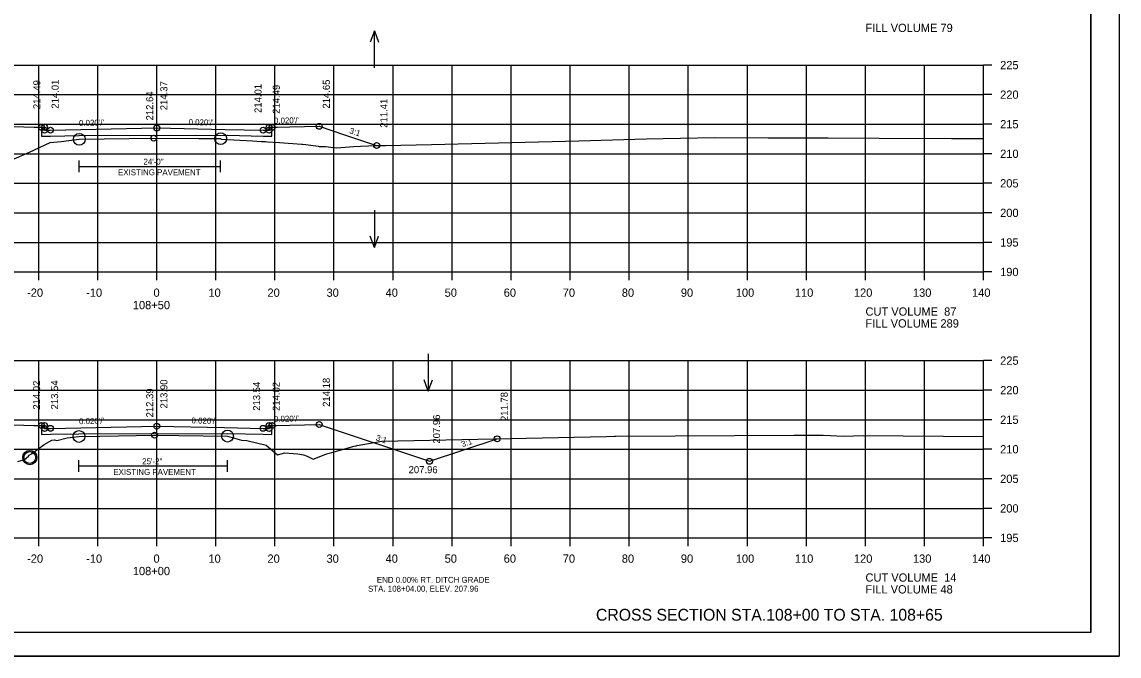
# Model space of a CAD drawing. Extents: x 1368968 to 1369915, y 377395 to 380381.
# Drawn here: x 1369115.3 to 1369301.1, y 379327.7 to 379435 of the extents above; entities that cross this region are included whole.
import ezdxf

# ---------------------------------------------------------------- set-up
doc = ezdxf.new("R2010")
doc.units = 0
for name, color, linetype in [('S_BORDER_NO_PLOT', 7, 'Continuous'), ('S_BREAKLINE_ANNOT', 7, 'Continuous'), ('S_BRIDGE', 7, 'Continuous'), ('S_BRIDGE_ANNOT', 7, 'Continuous'), ('S_CONTOUR_MAJOR', 7, 'Continuous'), ('S_CONTOUR_MINOR', 7, 'Continuous'), ('S_CROSS_DRAIN', 7, 'Continuous'), ('S_CTL_TABLE', 7, 'Continuous'), ('S_CURB_ANNOT', 7, 'Continuous'), ('S_DITCHLINE_ANNOT', 7, 'Continuous'), ('S_DROP_INLET', 7, 'Continuous'), ('S_EXIST_ROW_ANNOT', 7, 'Continuous'), ('S_EXISTING_ALIGNMENT', 7, 'Continuous'), ('S_EXISTING_ALIGNMENT_ANNOT', 7, 'Continuous'), ('S_FENCE', 7, 'Continuous')]:
    doc.layers.add(name, color=color, linetype=linetype)

msp = doc.modelspace()

# ---------------------------------------------------------------- linework, layer by layer
at = {"layer": 'S_BORDER_NO_PLOT'}
for points in [[(1369118.62, 379417.2), (1369118.63, 379415.69), (1369120.13, 379415.72), (1369125, 379415.82), (1369150.13, 379415.84), (1369156.13, 379415.72), (1369157.63, 379415.69), (1369157.64, 379417.2)], [(1369118.62, 379366.74), (1369118.63, 379365.23), (1369120.13, 379365.26), (1369124.95, 379365.35), (1369150.13, 379365.38), (1369156.13, 379365.26), (1369157.63, 379365.23), (1369157.64, 379366.74)]]:
    msp.add_lwpolyline(points, dxfattribs=at)
at = {"layer": 'S_BREAKLINE_ANNOT'}
for p, q in [((1369278.13, 379392.72), (1369278.13, 379427.72)), ((1369279.53, 379427.72), (1369278.13, 379427.72)), ((1369279.53, 379422.72), (1369278.13, 379422.72)), ((1369279.53, 379417.72), (1369278.13, 379417.72)), ((1369279.53, 379412.72), (1369278.13, 379412.72)), ((1369279.53, 379407.72), (1369278.13, 379407.72)), ((1369279.53, 379402.72), (1369278.13, 379402.72)), ((1369279.53, 379397.72), (1369278.13, 379397.72)), ((1368998.13, 379392.72), (1369278.13, 379392.72)), ((1369118.13, 379391.32), (1369118.13, 379392.72)), ((1369128.13, 379391.32), (1369128.13, 379392.72)), ((1369138.13, 379391.32), (1369138.13, 379392.72)), ((1369148.13, 379391.32), (1369148.13, 379392.72)), ((1369158.13, 379391.32), (1369158.13, 379392.72)), ((1369168.13, 379391.32), (1369168.13, 379392.72)), ((1369178.13, 379391.32), (1369178.13, 379392.72)), ((1369188.13, 379391.32), (1369188.13, 379392.72)), ((1369198.13, 379391.32), (1369198.13, 379392.72)), ((1369208.13, 379391.32), (1369208.13, 379392.72)), ((1369218.13, 379391.32), (1369218.13, 379392.72)), ((1369228.13, 379391.32), (1369228.13, 379392.72)), ((1369238.13, 379391.32), (1369238.13, 379392.72)), ((1369248.13, 379391.32), (1369248.13, 379392.72)), ((1369258.13, 379391.32), (1369258.13, 379392.72)), ((1369268.13, 379391.32), (1369268.13, 379392.72)), ((1369278.13, 379391.32), (1369278.13, 379392.72)), ((1369279.53, 379392.72), (1369278.13, 379392.72)), ((1369278.13, 379347.72), (1369278.13, 379377.72)), ((1369279.53, 379377.72), (1369278.13, 379377.72)), ((1369279.53, 379372.72), (1369278.13, 379372.72)), ((1369279.53, 379367.72), (1369278.13, 379367.72)), ((1369279.53, 379362.72), (1369278.13, 379362.72)), ((1369279.53, 379357.72), (1369278.13, 379357.72)), ((1369279.53, 379352.72), (1369278.13, 379352.72)), ((1368998.13, 379347.72), (1369278.13, 379347.72)), ((1369118.13, 379346.32), (1369118.13, 379347.72)), ((1369128.13, 379346.32), (1369128.13, 379347.72)), ((1369138.13, 379346.32), (1369138.13, 379347.72)), ((1369148.13, 379346.32), (1369148.13, 379347.72)), ((1369158.13, 379346.32), (1369158.13, 379347.72)), ((1369168.13, 379346.32), (1369168.13, 379347.72)), ((1369178.13, 379346.32), (1369178.13, 379347.72)), ((1369188.13, 379346.32), (1369188.13, 379347.72)), ((1369198.13, 379346.32), (1369198.13, 379347.72)), ((1369208.13, 379346.32), (1369208.13, 379347.72)), ((1369218.13, 379346.32), (1369218.13, 379347.72)), ((1369228.13, 379346.32), (1369228.13, 379347.72)), ((1369238.13, 379346.32), (1369238.13, 379347.72)), ((1369248.13, 379346.32), (1369248.13, 379347.72)), ((1369258.13, 379346.32), (1369258.13, 379347.72)), ((1369268.13, 379346.32), (1369268.13, 379347.72)), ((1369278.13, 379346.32), (1369278.13, 379347.72)), ((1369279.53, 379347.72), (1369278.13, 379347.72))]:
    msp.add_line(p, q, dxfattribs=at)
at = {"layer": 'S_BRIDGE_ANNOT'}
for q in [(1369296.31, 379537.18), (1368980.13, 379331.72)]:
    msp.add_line((1369296.31, 379331.72), q, dxfattribs=at)
at = {"layer": 'S_CROSS_DRAIN'}
for p, q in [((1369125, 379410.59), (1369148.94, 379410.59)), ((1369124.95, 379359.89), (1369150.11, 379359.89))]:
    msp.add_line(p, q, dxfattribs=at)
at = {"layer": 'S_CTL_TABLE'}
for points in [[(1369113.45, 379411.63), (1369116.56, 379413.01), (1369120.07, 379414.61), (1369121.93, 379414.82), (1369125, 379415.17), (1369129.2, 379415.24), (1369137.62, 379415.36), (1369145.24, 379415.32), (1369148.94, 379415.28), (1369149.02, 379415.21), (1369154.34, 379414.93), (1369155.87, 379414.82), (1369156.54, 379414.77), (1369156.89, 379414.75), (1369157.83, 379414.68), (1369158.9, 379414.61), (1369162.64, 379414.35), (1369162.83, 379414.33), (1369163.38, 379414.26), (1369165.44, 379413.99), (1369165.65, 379413.97), (1369166.69, 379413.96), (1369168.57, 379413.71), (1369171.51, 379413.96), (1369172.64, 379413.98), (1369175.35, 379414.13), (1369176.87, 379414.09), (1369184.62, 379414.31), (1369209.58, 379414.92), (1369221.02, 379415.26), (1369232.6, 379415.47), (1369241.67, 379415.44), (1369251.82, 379415.39), (1369260.46, 379415.38), (1369272.71, 379415.29), (1369278.13, 379415.29)], [(1369114.6, 379360.67), (1369115.74, 379360.98), (1369116.42, 379361.55), (1369116.54, 379361.72), (1369116.92, 379361.94), (1369119.08, 379363.55), (1369120.38, 379364.26), (1369120.79, 379364.31), (1369121.19, 379364.21), (1369122.98, 379364.66), (1369124.95, 379364.89), (1369128.49, 379364.95), (1369137.76, 379365.11), (1369141.89, 379365.06), (1369150.11, 379364.95), (1369152.5, 379364.24), (1369153.37, 379364.21), (1369156.63, 379363.4), (1369158.57, 379361.77), (1369159.79, 379362.09), (1369162.02, 379361.96), (1369162.96, 379361.8), (1369163.61, 379361.54), (1369164.58, 379361.06), (1369165.6, 379361.44), (1369166.85, 379361.94), (1369167.76, 379362.16), (1369171.53, 379363.23), (1369171.86, 379363.31), (1369171.94, 379363.33), (1369172.05, 379363.35), (1369176.25, 379364.09), (1369214.23, 379364.89), (1369215.64, 379364.91), (1369215.83, 379364.92), (1369245.98, 379365.08), (1369250.94, 379365.08), (1369254.45, 379364.96), (1369257.71, 379365.03), (1369278.13, 379364.87)]]:
    msp.add_lwpolyline(points, dxfattribs=at)
at = {"layer": 'S_CURB_ANNOT'}
for points in [[(1369074.64, 379412.29), (1369078.38, 379411.04), (1369085.02, 379408.83), (1369110.62, 379417.36), (1369110.62, 379417.36), (1369115.62, 379417.26), (1369117.36, 379417.23), (1369118.62, 379417.2), (1369119.12, 379417.2), (1369119.13, 379416.7), (1369119.73, 379416.72), (1369120.13, 379416.72), (1369138.13, 379417.08), (1369149.71, 379416.85), (1369156.13, 379416.72), (1369156.6, 379416.72), (1369157.13, 379416.7), (1369157.14, 379417.2), (1369157.64, 379417.2), (1369158.5, 379417.22), (1369160.64, 379417.26), (1369165.64, 379417.36), (1369169.93, 379415.94), (1369175.36, 379414.12)], [(1369110.62, 379366.9), (1369115.62, 379366.8), (1369117.31, 379366.77), (1369118.62, 379366.74), (1369119.12, 379366.74), (1369119.13, 379366.24), (1369119.74, 379366.25), (1369120.13, 379366.26), (1369120.14, 379366.26), (1369138.13, 379366.62), (1369138.14, 379366.62), (1369149.59, 379366.39), (1369156.13, 379366.26), (1369156.61, 379366.25), (1369157.13, 379366.24), (1369157.14, 379366.74), (1369157.64, 379366.74), (1369158.45, 379366.75), (1369160.64, 379366.8), (1369165.64, 379366.9), (1369184.3, 379360.68), (1369195.77, 379364.5)]]:
    msp.add_lwpolyline(points, dxfattribs=at)
at = {"layer": 'S_DITCHLINE_ANNOT'}
for p, q in [((1368998.13, 379427.72), (1369278.13, 379427.72)), ((1369118.13, 379392.72), (1369118.13, 379427.72)), ((1369128.13, 379392.72), (1369128.13, 379427.72)), ((1369138.13, 379392.72), (1369138.13, 379427.72)), ((1369148.13, 379392.72), (1369148.13, 379427.72)), ((1369158.13, 379392.72), (1369158.13, 379427.72)), ((1369168.13, 379392.72), (1369168.13, 379427.72)), ((1369178.13, 379392.72), (1369178.13, 379427.72)), ((1369188.13, 379392.72), (1369188.13, 379427.72)), ((1369198.13, 379392.72), (1369198.13, 379427.72)), ((1369208.13, 379392.72), (1369208.13, 379427.72)), ((1369218.13, 379392.72), (1369218.13, 379427.72)), ((1369228.13, 379392.72), (1369228.13, 379427.72)), ((1369238.13, 379392.72), (1369238.13, 379427.72)), ((1369248.13, 379392.72), (1369248.13, 379427.72)), ((1369258.13, 379392.72), (1369258.13, 379427.72)), ((1369268.13, 379392.72), (1369268.13, 379427.72)), ((1369278.13, 379392.72), (1369278.13, 379427.72)), ((1368998.13, 379422.72), (1369278.13, 379422.72)), ((1368998.13, 379417.72), (1369278.13, 379417.72)), ((1368998.13, 379412.72), (1369278.13, 379412.72)), ((1368998.13, 379407.72), (1369278.13, 379407.72)), ((1368998.13, 379402.72), (1369278.13, 379402.72)), ((1368998.13, 379397.72), (1369278.13, 379397.72)), ((1368998.13, 379392.72), (1369278.13, 379392.72)), ((1368998.13, 379377.72), (1369278.13, 379377.72)), ((1369118.13, 379347.72), (1369118.13, 379377.72)), ((1369128.13, 379347.72), (1369128.13, 379377.72)), ((1369138.13, 379347.72), (1369138.13, 379377.72)), ((1369148.13, 379347.72), (1369148.13, 379377.72)), ((1369158.13, 379347.72), (1369158.13, 379377.72)), ((1369168.13, 379347.72), (1369168.13, 379377.72)), ((1369178.13, 379347.72), (1369178.13, 379377.72)), ((1369188.13, 379347.72), (1369188.13, 379377.72)), ((1369198.13, 379347.72), (1369198.13, 379377.72)), ((1369208.13, 379347.72), (1369208.13, 379377.72)), ((1369218.13, 379347.72), (1369218.13, 379377.72)), ((1369228.13, 379347.72), (1369228.13, 379377.72)), ((1369238.13, 379347.72), (1369238.13, 379377.72)), ((1369248.13, 379347.72), (1369248.13, 379377.72)), ((1369258.13, 379347.72), (1369258.13, 379377.72)), ((1369268.13, 379347.72), (1369268.13, 379377.72)), ((1369278.13, 379347.72), (1369278.13, 379377.72)), ((1368998.13, 379372.72), (1369278.13, 379372.72)), ((1368998.13, 379367.72), (1369278.13, 379367.72)), ((1368998.13, 379362.72), (1369278.13, 379362.72)), ((1368998.13, 379357.72), (1369278.13, 379357.72)), ((1368998.13, 379352.72), (1369278.13, 379352.72)), ((1368998.13, 379347.72), (1369278.13, 379347.72))]:
    msp.add_line(p, q, dxfattribs=at)
at = {"layer": 'S_DROP_INLET'}
msp.add_line((1368967.73, 379327.74), (1369301.07, 379327.74), dxfattribs=at)
for points in [[(1368967.73, 379541.07), (1369301.07, 379541.07), (1369301.07, 379327.74), (1368967.73, 379327.74)], [(1369214.05, 379537.18), (1369214.05, 379527.3), (1369249.79, 379527.3), (1369249.79, 379524.38), (1369272.99, 379524.38), (1369272.99, 379500.05), (1369296.31, 379500.05), (1369296.31, 379331.72), (1368980.13, 379331.72), (1368980.13, 379537.18)]]:
    msp.add_lwpolyline(points, close=True, dxfattribs=at)
for centre, radius in [((1369118.62, 379417.2), 0.5), ((1369119.12, 379417.2), 0.5), ((1369119.13, 379416.7), 0.5), ((1369120.13, 379416.72), 0.5), ((1369120.13, 379416.72), 0.5), ((1369138.13, 379417.08), 0.5), ((1369156.13, 379416.72), 0.5), ((1369156.13, 379416.72), 0.5), ((1369157.13, 379416.7), 0.5), ((1369157.14, 379417.2), 0.5), ((1369157.64, 379417.2), 0.5), ((1369165.64, 379417.36), 0.5), ((1369125, 379415.17), 1), ((1369137.62, 379415.36), 0.5), ((1369148.94, 379415.28), 1), ((1369175.36, 379414.12), 0.5), ((1369118.62, 379366.74), 0.5), ((1369119.12, 379366.74), 0.5), ((1369119.13, 379366.24), 0.5), ((1369120.13, 379366.26), 0.5), ((1369120.13, 379366.26), 0.5), ((1369138.13, 379366.62), 0.5), ((1369156.13, 379366.26), 0.5), ((1369156.13, 379366.26), 0.5), ((1369157.13, 379366.24), 0.5), ((1369157.14, 379366.74), 0.5), ((1369157.64, 379366.74), 0.5), ((1369165.64, 379366.9), 0.5), ((1369124.95, 379364.89), 1), ((1369137.76, 379365.11), 0.5), ((1369150.11, 379364.95), 1), ((1369195.77, 379364.5), 0.5), ((1369116.63, 379361.32), 1.21), ((1369184.3, 379360.68), 0.5)]:
    msp.add_circle(centre, radius, dxfattribs=at)
at = {"layer": 'S_EXIST_ROW_ANNOT'}
for p, q in [((1369125, 379409.59), (1369125, 379411.59)), ((1369148.94, 379409.59), (1369148.94, 379411.59)), ((1369124.95, 379358.89), (1369124.95, 379360.89)), ((1369150.11, 379358.89), (1369150.11, 379360.89))]:
    msp.add_line(p, q, dxfattribs=at)
msp.add_circle((1369116.63, 379361.32), 1, dxfattribs=at)
at = {"layer": 'S_EXISTING_ALIGNMENT'}
for p, q in [((1369174.98, 379433.52), (1369174.28, 379431.59)), ((1369174.98, 379427.23), (1369174.98, 379433.52)), ((1369174.98, 379433.52), (1369175.68, 379431.59)), ((1369174.98, 379403.15), (1369174.98, 379396.87)), ((1369174.98, 379396.87), (1369174.28, 379398.79)), ((1369174.98, 379396.87), (1369175.68, 379398.79)), ((1369184.1, 379378.84), (1369184.1, 379372.55)), ((1369184.1, 379372.55), (1369183.4, 379374.48)), ((1369184.1, 379372.55), (1369184.8, 379374.48))]:
    msp.add_line(p, q, dxfattribs=at)
at = {"layer": 'S_EXISTING_ALIGNMENT_ANNOT'}
for p, q in [((1369138.13, 379415.36), (1369138.13, 379425.36)), ((1369138.13, 379365.11), (1369138.13, 379375.11))]:
    msp.add_line(p, q, dxfattribs=at)

# ---------------------------------------------------------------- texts
at = {"layer": 'S_BRIDGE'}
for s, p in [('FILL VOLUME 79', (1369258.13, 379433.32)), ('225', (1369280.93, 379427.02)), ('220', (1369280.93, 379422.02)), ('215', (1369280.93, 379417.02)), ('210', (1369280.93, 379412.02)), ('205', (1369280.93, 379407.02)), ('200', (1369280.93, 379402.02)), ('195', (1369280.93, 379397.02)), ('190', (1369280.93, 379392.02)), ('-20', (1369116.17, 379388.52)), ('-10', (1369126.17, 379388.52)), ('0', (1369137.57, 379388.52)), ('10', (1369146.87, 379388.52)), ('20', (1369156.87, 379388.52)), ('30', (1369166.87, 379388.52)), ('40', (1369176.87, 379388.52)), ('50', (1369186.87, 379388.52)), ('60', (1369196.87, 379388.52)), ('70', (1369206.87, 379388.52)), ('80', (1369216.87, 379388.52)), ('90', (1369226.87, 379388.52)), ('100', (1369236.17, 379388.52)), ('110', (1369246.17, 379388.52)), ('120', (1369256.17, 379388.52)), ('130', (1369266.17, 379388.52)), ('140', (1369276.17, 379388.52)), ('108+50', (1369134.07, 379386.42)), ('CUT VOLUME  87', (1369258.13, 379385.32)), ('FILL VOLUME 289', (1369258.13, 379383.32)), ('225', (1369280.93, 379377.02)), ('220', (1369280.93, 379372.02)), ('215', (1369280.93, 379367.02)), ('210', (1369280.93, 379362.02)), ('205', (1369280.93, 379357.02)), ('200', (1369280.93, 379352.02)), ('195', (1369280.93, 379347.02)), ('-20', (1369116.17, 379343.52)), ('-10', (1369126.17, 379343.52)), ('0', (1369137.57, 379343.52)), ('10', (1369146.87, 379343.52)), ('20', (1369156.87, 379343.52)), ('30', (1369166.87, 379343.52)), ('40', (1369176.87, 379343.52)), ('50', (1369186.87, 379343.52)), ('60', (1369196.87, 379343.52)), ('70', (1369206.87, 379343.52)), ('80', (1369216.87, 379343.52)), ('90', (1369226.87, 379343.52)), ('100', (1369236.17, 379343.52)), ('110', (1369246.17, 379343.52)), ('120', (1369256.17, 379343.52)), ('130', (1369266.17, 379343.52)), ('140', (1369276.17, 379343.52)), ('108+00', (1369134.07, 379341.42)), ('CUT VOLUME  14', (1369258.13, 379340.32)), ('FILL VOLUME 48', (1369258.13, 379338.32))]:
    msp.add_text(s, height=1.4, dxfattribs=at).set_placement(p)
at = {"layer": 'S_CONTOUR_MAJOR'}
for s, p in [('END 0.00% RT. DITCH GRADE', (1369175.39, 379340.13)), ('STA. 108+04.00, ELEV. 207.96', (1369173.9, 379338.63))]:
    msp.add_text(s, height=1, dxfattribs=at).set_placement(p)
at = {"layer": 'S_CONTOUR_MINOR'}
msp.add_text('CROSS SECTION STA.108+00 TO STA. 108+65', height=2, dxfattribs=at).set_placement((1369212.49, 379333.72))
at = {"layer": 'S_DROP_INLET'}
msp.add_text('207.96', height=1.2, dxfattribs=at).set_placement((1369180.77, 379358.67))
at = {"layer": 'S_EXIST_ROW_ANNOT'}
for s, p in [('24\'-0"', (1369135.87, 379410.89)), ('EXISTING PAVEMENT', (1369131.57, 379409.08)), ('25\'-2"', (1369135.66, 379360.19)), ('EXISTING PAVEMENT', (1369130.77, 379358.38))]:
    msp.add_text(s, height=1, dxfattribs=at).set_placement(p)
at = {"layer": 'S_EXISTING_ALIGNMENT_ANNOT'}
for s, p in [('214.49', (1369118.42, 379420.27)), ('214.01', (1369121.51, 379420.35)), ('214.37', (1369139.93, 379420.08)), ('214.01', (1369155.87, 379419.62)), ('214.49', (1369158.96, 379419.48)), ('214.65', (1369167.44, 379420.36)), ('212.64', (1369137.53, 379418.36)), ('211.41', (1369177.16, 379417.12)), ('214.02', (1369118.38, 379369.42)), ('213.54', (1369121.42, 379369.46)), ('213.90', (1369139.93, 379369.62)), ('213.54', (1369155.63, 379369.23)), ('214.02', (1369158.95, 379369.2)), ('214.18', (1369167.44, 379369.9)), ('212.39', (1369137.53, 379368.11)), ('211.78', (1369197.57, 379367.5)), ('207.96', (1369186.1, 379363.68))]:
    msp.add_text(s, height=1.2, rotation=90, dxfattribs=at).set_placement(p)
at = {"layer": 'S_FENCE'}
for s, rotation, p in [("0.020'/'", 1.1457, (1369124.97, 379417.42)), ("0.020'/'", 358.8543, (1369143.5, 379417.58)), ("0.020'/'", 1.1458, (1369157.98, 379417.81)), ('3:1', 341.5633, (1369170.66, 379416.22)), ("0.020'/'", 1.1458, (1369157.98, 379367.35)), ("0.020'/'", 1.1457, (1369124.97, 379366.96)), ("0.020'/'", 358.8542, (1369144, 379367.1)), ('3:1', 341.5651, (1369175.13, 379364.26)), ('3:1', 18.4338, (1369189.88, 379363.06))]:
    msp.add_text(s, height=1, rotation=rotation, dxfattribs=at).set_placement(p)

doc.saveas('drawing.dxf')
